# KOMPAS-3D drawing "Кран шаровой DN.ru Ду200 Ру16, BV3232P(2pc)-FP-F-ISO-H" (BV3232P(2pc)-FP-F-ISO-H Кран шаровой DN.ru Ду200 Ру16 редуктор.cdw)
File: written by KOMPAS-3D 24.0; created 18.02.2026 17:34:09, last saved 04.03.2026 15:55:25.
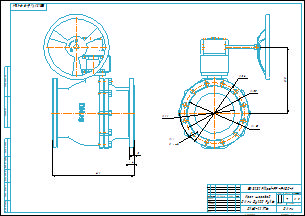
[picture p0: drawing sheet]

Document properties: Автор: R2D2; Форматы листов документа: A2; Полное имя файла: BV3232P(2pc)-FP-F-ISO-H Кран шаровой DN.ru Ду200 Ру16 редуктор.m3d; Масса: 72; Наименование: Кран шаровой DN.ru Ду200 Ру16; Количество листов документа: 1; Примечание: D160-22176

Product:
- Part/product: Кран шаровой DN.ru Ду200 Ру16  | designation BV3232P(2pc)-FP-F-ISO-H
    Масса: 72
    Раздел спецификации: Прочие изделия
    Примечание: D160-22176

Views: Вид 1, Справа, Проекционный вид 2
Referenced files in E:\Работа\Зайцев\BV3232P(2pc)-FP-F-ISO-H Кран шаровой DN.ru Ду15-300 Ру16-40\DN200 PN16 редуктор\: BV3232P(2pc)-FP-F-ISO-H Кран шаровой DN.ru Ду200 Ру16 редуктор.m3d
Referenced files in E:\Работа\Зайцев\Для компаса\: чертеж DN.ru А3.cdt
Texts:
  BV3232P(2pc)-FP-F-ISO-H
  чертеж DN.ru А3.cdt
  Кран шаровой
  DN.ru Ду200 Ру16
  Кран шаровой DN.ru Ду200 Ру16
  BV3232P(2pc)-FP-F-ISO-H Кран шаровой DN.ru Ду200 Ру16
Dimensions and other numbers on the sheet: 0; 3; 2; 4; 400; 24; 323; 340; 295; 268; 200; 22; 12 отв.; 1:2,5; 1; 72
